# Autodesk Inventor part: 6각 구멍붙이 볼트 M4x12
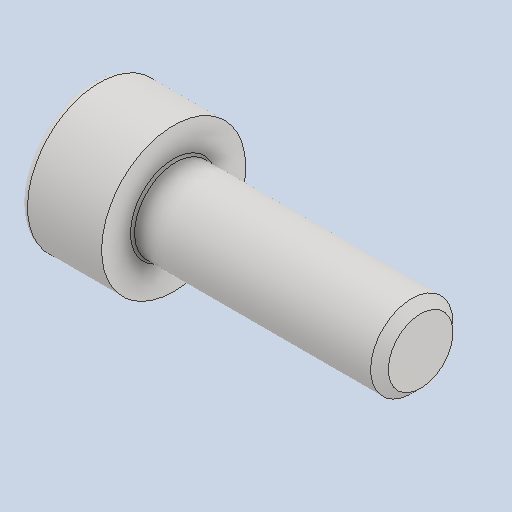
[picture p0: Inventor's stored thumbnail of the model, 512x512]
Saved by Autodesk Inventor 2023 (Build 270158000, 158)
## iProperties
Created: 2025-03
Part Number: 6각 구멍붙이 볼트 M4x12
Material: 스테인리스강
Description: 6각 소켓 머리 캡 나사
Document SubType Name: Modeling
Designer: ADMIN_PC
Density: 8.08 g/cm^3
Appearance: 기본값
Author: jhkim
Sending System: Autodesk Inventor 2025
Preprocessor: ST-DEVELOPER v20
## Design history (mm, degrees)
feature "Solid1"
node "솔리드1"
